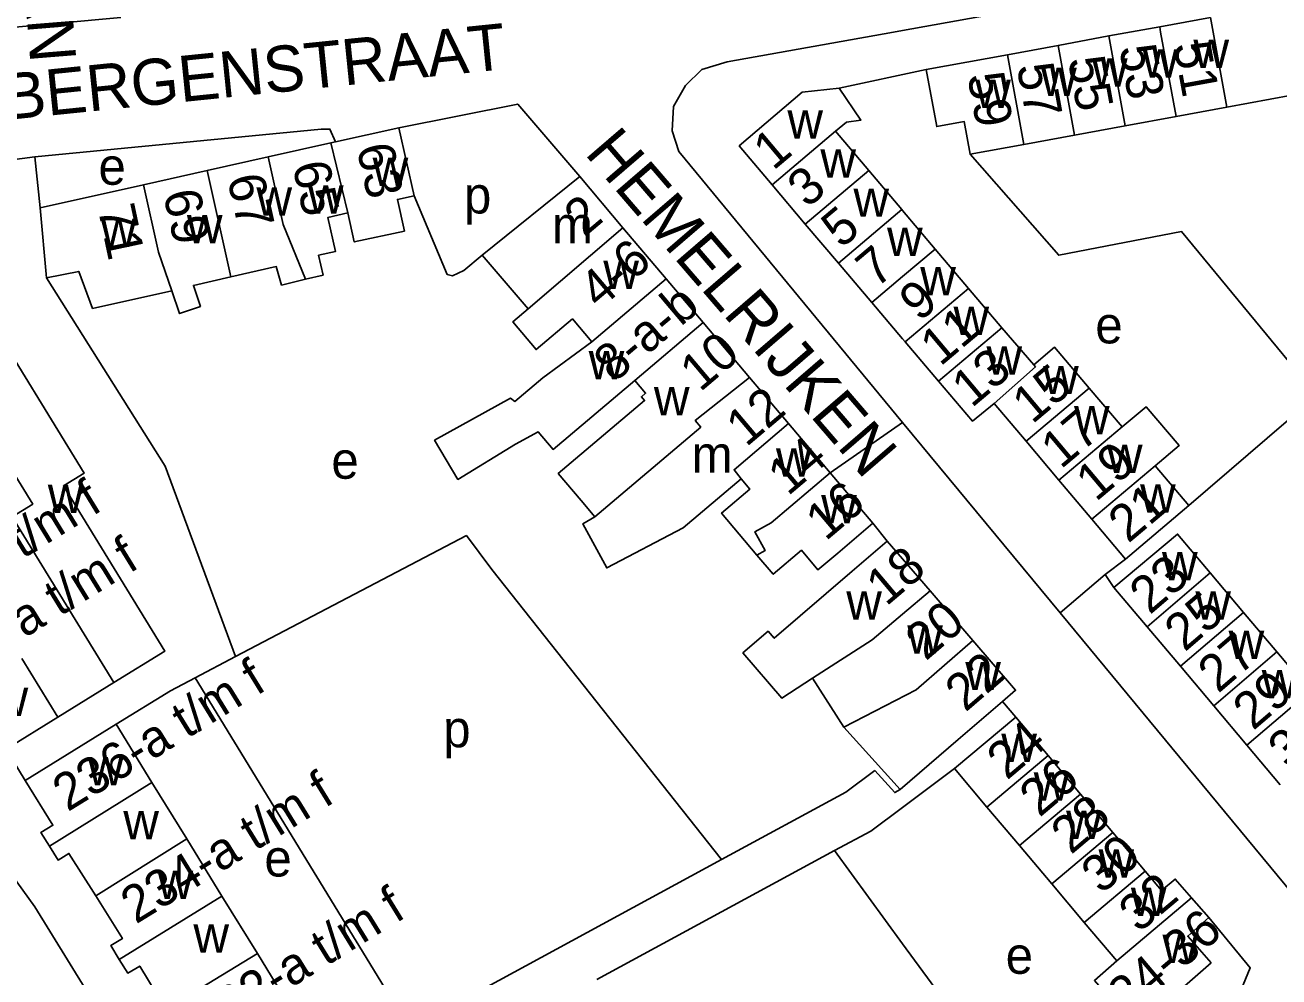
# Model space of a CAD drawing. Extents: x 159902 to 161769, y 383692 to 384875.
# Drawn here: x 160604.7 to 160740.8, y 384397.4 to 384500.8 of the extents above; entities that cross this region are included whole.
import ezdxf

# ---------------------------------------------------------------- set-up
doc = ezdxf.new("R2010")
doc.units = 0
for name, color, linetype in [('BLT_Basislijn', 7, 'Continuous'), ('BLT_Bebouwing', 7, 'Continuous'), ('BLT_Centroide', 7, 'Continuous'), ('BLT_Huisnummer', 7, 'Continuous'), ('BLT_Huisnummer_ tussenligend', 7, 'Continuous'), ('BLT_Huisnummer_reeks', 7, 'Continuous'), ('BLT_Onderverdeling_panden', 7, 'Continuous'), ('BLT_Straatnaam', 7, 'Continuous'), ('BLT_Vlakafsluiter', 7, 'Continuous')]:
    doc.layers.add(name, color=color, linetype=linetype)

msp = doc.modelspace()

# ---------------------------------------------------------------- linework, layer by layer
at = {"layer": 'BLT_Basislijn'}
for p, q in [((160700, 384500.18), (160699, 384500)), ((160702.56, 384495.92), (160693.11, 384493.92)), ((160595.93, 384485.18), (160605.79, 384486.44)), ((160731.05, 384448.61), (160744.94, 384460.54)), ((160700, 384457.63), (160717.09, 384436.96)), ((160696.77, 384446.67), (160698.32, 384444.75)), ((160655.4, 384441.64), (160680.34, 384410.17)), ((160721.97, 384441.1), (160724.19, 384442.79)), ((160717.09, 384436.96), (160721.97, 384441.1)), ((160722.94, 384439.7), (160721.97, 384441.1)), ((160717.09, 384436.96), (160746.97, 384400.81)), ((160627.59, 384432.2), (160623.2, 384429.9)), ((160614.39, 384429.39), (160608.3, 384425.63)), ((160623.2, 384429.9), (160645.9, 384392.82)), ((160710.85, 384427.34), (160712.27, 384425.64)), ((160604.77, 384418.77), (160602.68, 384422.17)), ((160700, 384415.84), (160705.63, 384420.04)), ((160666.8, 384397.15), (160692.62, 384411.14)), ((160692.62, 384411.14), (160700, 384401.04)), ((160646.52, 384391.81), (160680.34, 384410.17)), ((160700, 384401.04), (160706.82, 384391.71))]:
    msp.add_line(p, q, dxfattribs=at)
for points in [[(160758.87, 384500), (160751.1, 384509.34), (160700, 384500.18)], [(160699, 384500), (160680.95, 384496.77), (160678.22, 384495.92), (160676.42, 384494.2), (160675.14, 384491.91), (160674.99, 384489.28), (160675.71, 384487.02), (160700, 384457.63)], [(160664.95, 384484.33), (160658.23, 384492.18), (160645.33, 384489.61)], [(160638.44, 384488.07), (160637.84, 384489.47), (160636.89, 384489.44), (160605.79, 384486.44)], [(160707.33, 384486.73), (160716.95, 384475.77), (160730.27, 384478.33), (160744.94, 384460.54)], [(160605.79, 384486.44), (160606.39, 384480.92)], [(160646.98, 384482.23), (160650.55, 384473.68), (160651.15, 384473.52), (160652.37, 384474.11), (160654.36, 384475.79)], [(160607.09, 384473.32), (160619.95, 384452.88), (160627.59, 384432.2)], [(160655.4, 384441.64), (160652.65, 384445.34), (160627.59, 384432.2)], [(160623.2, 384429.9), (160620.54, 384428.5), (160614.63, 384424.85)], [(160680.34, 384410.17), (160693.84, 384417.49), (160696.99, 384419.84)], [(160699.73, 384417.78), (160699.14, 384417.45), (160696.99, 384419.84)], [(160692.62, 384411.14), (160696.54, 384413.26), (160700, 384415.84)], [(160644.83, 384338.21), (160643.59, 384342.14), (160640.8, 384348.26), (160626.55, 384371.32), (160620.56, 384381.08), (160605.79, 384405.03), (160602.56, 384409.58), (160597.68, 384415)], [(160736.44, 384395.35), (160737.72, 384398.4), (160733.22, 384403.87)]]:
    msp.add_lwpolyline(points, dxfattribs=at)
at = {"layer": 'BLT_Bebouwing'}
for p, q in [((160733.41, 384501.57), (160727.9, 384500.58)), ((160727.9, 384500.58), (160722.39, 384499.57)), ((160722.39, 384499.57), (160716.88, 384498.55)), ((160711.38, 384497.54), (160702.56, 384495.92)), ((160716.88, 384498.55), (160711.38, 384497.54)), ((160693.11, 384493.92), (160689.09, 384493.46)), ((160724.17, 384489.83), (160729.67, 384490.84)), ((160729.67, 384490.84), (160735.18, 384491.85)), ((160638.44, 384488.07), (160645.33, 384489.61)), ((160696.32, 384484.95), (160692.71, 384489.22)), ((160718.66, 384488.81), (160724.17, 384489.83)), ((160631.12, 384486.44), (160637.94, 384487.96)), ((160637.94, 384487.96), (160638.44, 384488.07)), ((160713.15, 384487.8), (160718.66, 384488.81)), ((160707.33, 384486.73), (160713.15, 384487.8)), ((160624.5, 384484.96), (160631.12, 384486.44)), ((160617.61, 384483.42), (160624.5, 384484.96)), ((160669.64, 384478.75), (160664.95, 384484.33)), ((160699.9, 384480.73), (160696.32, 384484.95)), ((160685.82, 384483.42), (160689.43, 384479.16)), ((160700, 384480.61), (160699.9, 384480.73)), ((160703.54, 384476.43), (160700, 384480.61)), ((160674.34, 384473.2), (160669.64, 384478.75)), ((160689.43, 384479.16), (160693.05, 384474.9)), ((160659.36, 384469.95), (160654.36, 384475.79)), ((160707.15, 384472.16), (160703.54, 384476.43)), ((160693.05, 384474.9), (160696.66, 384470.64)), ((160678.34, 384468.46), (160674.34, 384473.2)), ((160696.66, 384470.64), (160700, 384466.7)), ((160683.38, 384462.5), (160678.34, 384468.46)), ((160714.24, 384463.89), (160710.77, 384467.9)), ((160700, 384466.7), (160700.27, 384466.38)), ((160700.27, 384466.38), (160703.89, 384462.11)), ((160687.62, 384457.51), (160683.38, 384462.5)), ((160723.82, 384457.13), (160720.25, 384461.35)), ((160709.92, 384459.68), (160713.39, 384455.58)), ((160692.14, 384452.15), (160687.62, 384457.51)), ((160713.39, 384455.58), (160716.96, 384451.35)), ((160731.05, 384448.61), (160727.4, 384452.91)), ((160696.77, 384446.67), (160692.14, 384452.15)), ((160716.96, 384451.35), (160720.53, 384447.13)), ((160724.19, 384442.79), (160731.05, 384448.61)), ((160720.53, 384447.13), (160724.19, 384442.79)), ((160700, 384442.8), (160698.32, 384444.75)), ((160702.97, 384439.35), (160700, 384442.8)), ((160737, 384437), (160733.39, 384441.29)), ((160707.61, 384433.95), (160702.97, 384439.35)), ((160740.61, 384432.72), (160737, 384437)), ((160726.54, 384435.43), (160730.15, 384431.15)), ((160744.21, 384428.44), (160740.61, 384432.72)), ((160604.39, 384431.98), (160608.3, 384425.63)), ((160730.15, 384431.15), (160733.76, 384426.86)), ((160693.6, 384424.55), (160690.21, 384429.85)), ((160706.04, 384423.2), (160710.85, 384427.34)), ((160733.76, 384426.86), (160737.37, 384422.58)), ((160608.3, 384425.63), (160602.68, 384422.17)), ((160705.63, 384420.04), (160712.27, 384425.64)), ((160712.27, 384425.64), (160715.78, 384421.46)), ((160614.63, 384424.85), (160604.77, 384418.77)), ((160618.52, 384418.53), (160614.63, 384424.85)), ((160693.6, 384424.55), (160699.73, 384417.78)), ((160706.04, 384423.2), (160699.73, 384417.78)), ((160737.37, 384422.58), (160740.97, 384418.3)), ((160715.78, 384421.46), (160719.3, 384417.28)), ((160709.15, 384415.86), (160705.63, 384420.04)), ((160622.29, 384412.43), (160618.52, 384418.53)), ((160719.3, 384417.28), (160722.81, 384413.1)), ((160712.67, 384411.69), (160709.15, 384415.86)), ((160722.81, 384413.1), (160726.32, 384408.92)), ((160626.12, 384406.2), (160622.29, 384412.43)), ((160716.19, 384407.52), (160712.67, 384411.69)), ((160719.71, 384403.35), (160716.19, 384407.52)), ((160629.97, 384399.96), (160626.12, 384406.2)), ((160731.34, 384406.02), (160723.23, 384399.17)), ((160723.23, 384399.17), (160719.71, 384403.35)), ((160633.67, 384393.94), (160629.97, 384399.96))]:
    msp.add_line(p, q, dxfattribs=at)
for points in [[(160702.56, 384495.92), (160703.7, 384489.74), (160706.68, 384490.28), (160707.33, 384486.73)], [(160689.09, 384493.46), (160682.26, 384487.63), (160685.82, 384483.42)], [(160693.11, 384493.92), (160695.47, 384490.44), (160693.89, 384490.21), (160692.71, 384489.22)], [(160735.18, 384491.85), (160744.6, 384493.58), (160748.37, 384489.06)], [(160645.33, 384489.61), (160646.98, 384482.23)], [(160664.95, 384484.33), (160654.36, 384475.79)], [(160606.39, 384480.92), (160617.61, 384483.42)], [(160639.78, 384480.37), (160640.47, 384477.21), (160645.92, 384478.39), (160645.17, 384481.83), (160646.98, 384482.23)], [(160607.09, 384473.32), (160606.39, 384480.92)], [(160635.19, 384473.16), (160637.09, 384473.62), (160636.61, 384475.76), (160638.44, 384476.17), (160637.61, 384479.88), (160639.78, 384480.37)], [(160627.08, 384473.41), (160632.01, 384474.53), (160632.58, 384472.53), (160635.19, 384473.16)], [(160620.67, 384471.91), (160612.08, 384469.99), (160610.57, 384474.01), (160607.09, 384473.32)], [(160620.67, 384471.91), (160621.51, 384469.43), (160623.78, 384470.21), (160623.01, 384472.49), (160627.08, 384473.41)], [(160710.77, 384467.9), (160707.15, 384472.16)], [(160614.39, 384429.39), (160619.93, 384432.8), (160608.9, 384450.73), (160611.17, 384452.13), (160600.08, 384470.15), (160594.52, 384466.73)], [(160666.26, 384466.37), (160664.15, 384468.86), (160660.21, 384465.53), (160657.68, 384468.53), (160659.36, 384469.95)], [(160594.52, 384466.73), (160605.58, 384448.76), (160603.33, 384447.37), (160614.39, 384429.39)], [(160670.92, 384462.18), (160662.06, 384454.69), (160660.45, 384456.59), (160657.97, 384455.25), (160651.72, 384451.44), (160649.19, 384455.68), (160657.43, 384460.25), (160657.92, 384459.91), (160660.93, 384462.46), (160666.26, 384466.37)], [(160720.25, 384461.35), (160716.49, 384465.78), (160714.24, 384463.89)], [(160714.24, 384463.89), (160714.42, 384463.67)], [(160670.92, 384462.18), (160672.1, 384460.78), (160671.65, 384460.4), (160671.99, 384460), (160662.62, 384452.07), (160665.1, 384449.14), (160666.58, 384447.39)], [(160703.89, 384462.11), (160707.59, 384457.75), (160709.92, 384459.68)], [(160727.4, 384452.91), (160730.01, 384455.1), (160726.43, 384459.32), (160723.82, 384457.13)], [(160682.48, 384451.51), (160676.18, 384446.18), (160667.88, 384441.82), (160665.28, 384446.61), (160666.58, 384447.39)], [(160684.19, 384443.23), (160680.35, 384447.78), (160683.43, 384450.39), (160682.48, 384451.51)], [(160696.77, 384446.67), (160692.95, 384443.44), (160690.8, 384441.62), (160689.02, 384443.74), (160685.96, 384441.15), (160684.19, 384443.23)], [(160690.21, 384429.85), (160686.88, 384427.7), (160682.67, 384432.6), (160685.4, 384434.95), (160686.06, 384434.2), (160694.53, 384441.49), (160698.32, 384444.75)], [(160733.39, 384441.29), (160729.84, 384445.51), (160722.94, 384439.7)], [(160722.94, 384439.7), (160726.54, 384435.43)], [(160710.85, 384427.34), (160712.26, 384428.55), (160707.61, 384433.95)], [(160604.77, 384418.77), (160607.77, 384413.89), (160606.47, 384413.11), (160607.4, 384411.61)], [(160607.4, 384411.61), (160608.33, 384410.12), (160609.51, 384410.83), (160612.41, 384406.22)], [(160726.32, 384408.92), (160728.1, 384406.8), (160729.59, 384408.05), (160731.34, 384406.02)], [(160612.41, 384406.22), (160615.31, 384401.6), (160614.05, 384400.84), (160614.97, 384399.34)], [(160733.22, 384403.87), (160731.34, 384406.02)], [(160733.49, 384398.96), (160730.94, 384401.87), (160733.22, 384403.87)], [(160614.97, 384399.34), (160615.89, 384397.85), (160617.19, 384398.61), (160620.02, 384393.93)], [(160723.23, 384399.17), (160720.82, 384397.03), (160725.36, 384391.84), (160733.49, 384398.96)]]:
    msp.add_lwpolyline(points, dxfattribs=at)
at = {"layer": 'BLT_Onderverdeling_panden'}
for p, q in [((160733.41, 384501.57), (160733.7, 384500)), ((160727.9, 384500.58), (160728, 384500)), ((160722.39, 384499.57), (160724.17, 384489.83)), ((160728, 384500), (160729.67, 384490.84)), ((160733.7, 384500), (160735.18, 384491.85)), ((160711.38, 384497.54), (160713.15, 384487.8)), ((160716.88, 384498.55), (160718.66, 384488.81)), ((160685.82, 384483.42), (160692.71, 384489.22)), ((160639.78, 384480.37), (160637.94, 384487.96)), ((160627.08, 384473.41), (160624.5, 384484.96)), ((160689.43, 384479.16), (160696.32, 384484.95)), ((160693.05, 384474.9), (160699.9, 384480.73)), ((160659.36, 384469.95), (160669.64, 384478.75)), ((160700, 384473.45), (160703.54, 384476.43)), ((160666.26, 384466.37), (160674.34, 384473.2)), ((160696.66, 384470.64), (160700, 384473.45)), ((160700.27, 384466.38), (160707.15, 384472.16)), ((160670.92, 384462.18), (160678.34, 384468.46)), ((160703.89, 384462.11), (160710.77, 384467.9)), ((160709.92, 384459.68), (160714.42, 384463.67)), ((160713.39, 384455.58), (160720.25, 384461.35)), ((160716.96, 384451.35), (160723.82, 384457.13)), ((160720.53, 384447.13), (160727.4, 384452.91)), ((160733.39, 384441.29), (160726.54, 384435.43)), ((160700, 384436.8), (160702.97, 384439.35)), ((160737, 384437), (160730.15, 384431.15)), ((160701.47, 384428.58), (160707.61, 384433.95)), ((160740.61, 384432.72), (160733.76, 384426.86)), ((160693.6, 384424.55), (160701.47, 384428.58)), ((160744.21, 384428.44), (160737.37, 384422.58)), ((160709.15, 384415.86), (160715.78, 384421.46)), ((160607.4, 384411.61), (160618.52, 384418.53)), ((160712.67, 384411.69), (160719.3, 384417.28)), ((160716.19, 384407.52), (160722.81, 384413.1)), ((160612.41, 384406.22), (160622.29, 384412.43)), ((160719.71, 384403.35), (160726.32, 384408.92)), ((160614.97, 384399.34), (160626.12, 384406.2)), ((160620.02, 384393.93), (160629.97, 384399.96))]:
    msp.add_line(p, q, dxfattribs=at)
for points in [[(160635.19, 384473.16), (160632.75, 384479.11), (160631.12, 384486.44)], [(160620.67, 384471.91), (160619.24, 384476.1), (160617.61, 384483.42)], [(160666.58, 384447.39), (160678.08, 384457.11), (160677.49, 384457.82), (160683.38, 384462.5)], [(160682.48, 384451.51), (160681.7, 384452.49), (160687.62, 384457.51)], [(160684.19, 384443.23), (160685.08, 384443.72), (160683.96, 384445.76), (160685.74, 384446.74), (160692.14, 384452.15)], [(160690.21, 384429.85), (160696.7, 384434.02), (160700, 384436.8)]]:
    msp.add_lwpolyline(points, dxfattribs=at)
at = {"layer": 'BLT_Vlakafsluiter'}
for p, q in [((160615.14, 384501.58), (160600.21, 384500.22)), ((160700, 384457.63), (160692.14, 384452.15))]:
    msp.add_line(p, q, dxfattribs=at)

# ---------------------------------------------------------------- texts
at = {"layer": 'BLT_Centroide'}
for s, p in [('w', (160731.56, 384496.08)), ('w', (160726.05, 384495.06)), ('w', (160715.03, 384493.06)), ('w', (160720.55, 384494.06)), ('w', (160707.88, 384491.77)), ('w', (160687.49, 384488.44)), ('e', (160612.71, 384483.42)), ('w', (160691.07, 384484.19)), ('w', (160642.47, 384483.28)), ('w', (160629.86, 384480.06)), ('w', (160635.45, 384480.28)), ('p', (160652.38, 384480.3)), ('w', (160694.66, 384479.94)), ('w', (160612.97, 384476.66)), ('w', (160622.31, 384477.06)), ('m', (160661.94, 384477.06)), ('w', (160698.31, 384475.69)), ('w', (160667.51, 384472.12)), ('w', (160701.91, 384471.41)), ('w', (160705.52, 384467.12)), ('e', (160720.91, 384466.2)), ('w', (160665.92, 384462.31)), ('w', (160709.1, 384462.81)), ('w', (160715.25, 384460.69)), ('w', (160673, 384458.38)), ('w', (160718.6, 384456.34)), ('m', (160677.09, 384452.16)), ('w', (160722.17, 384452.12)), ('e', (160637.99, 384451.51)), ('w', (160686.25, 384451.75)), ('w', (160607.22, 384447.78)), ('w', (160691.16, 384446.66)), ('w', (160725.77, 384447.84)), ('w', (160728.15, 384440.47)), ('w', (160693.88, 384436.22)), ('w', (160731.77, 384436.22)), ('w', (160700.5, 384432.53)), ('w', (160735.38, 384431.94)), ('w', (160706.8, 384428.56)), ('w', (160738.98, 384427.66)), ('w', (160601.22, 384425.75)), ('p', (160650.13, 384422.36)), ('w', (160710.71, 384420.75)), ('w', (160611.56, 384418.22)), ('w', (160714.23, 384416.56)), ('w', (160615.41, 384412.38)), ('w', (160717.74, 384412.41)), ('e', (160630.72, 384408.33)), ('w', (160721.26, 384408.22)), ('w', (160619.12, 384405.88)), ('w', (160724.77, 384404.06)), ('w', (160623.02, 384400.06)), ('e', (160711.18, 384397.77)), ('w', (160728.2, 384398.94))]:
    msp.add_text(s, height=4, dxfattribs=at).set_placement(p)
at = {"layer": 'BLT_Huisnummer'}
for s, rotation, p in [('53', 280.3225, (160723.49, 384498.31)), ('59', 280.3225, (160707.01, 384495.29)), ('63', 282.573, (160640.7, 384487.48)), ('1', 40.0727, (160685.95, 384484.89)), ('67', 282.5712, (160626.66, 384484.16)), ('71', 282.0197, (160612.62, 384480.87)), ('2', 40.2176, (160665.43, 384477.66)), ('5', 40.072, (160693.33, 384476.42)), ('9', 40.076, (160701.8, 384468.47)), ('13', 40.0664, (160707.49, 384459.13)), ('12', 40.2165, (160683.01, 384454.88)), ('17', 40.0705, (160717.17, 384452.48)), ('16', 40.21, (160691.64, 384444.67)), ('21', 40.0664, (160724.48, 384444.43)), ('23', 40.5495, (160726.82, 384436.68)), ('20', 40.7166, (160702.5, 384431.66)), ('27', 40.5495, (160734.24, 384428.14)), ('31', 40.4715, (160741.85, 384419.87)), ('24', 40.1467, (160711.31, 384418.72)), ('28', 40.1449, (160718.27, 384410.64)), ('32', 40.0069, (160725.63, 384402.13))]:
    msp.add_text(s, height=4, rotation=rotation, dxfattribs=at).set_placement(p)
at = {"layer": 'BLT_Huisnummer_ tussenligend'}
for s, rotation, p in [('51', 280.3225, (160729.38, 384498.62)), ('57', 280.3225, (160712.37, 384496.3)), ('55', 280.3225, (160717.93, 384497.04)), ('65', 282.573, (160633.74, 384485.56)), ('3', 40.0727, (160689.65, 384480.81)), ('69', 282.5712, (160619.71, 384482.48)), ('7', 40.072, (160697.11, 384472.11)), ('11', 40.076, (160704.08, 384463.63)), ('10', 40.2165, (160678.01, 384460.85)), ('15', 40.0664, (160714.06, 384457.36)), ('14', 40.2165, (160687.54, 384449.56)), ('19', 40.0705, (160720.97, 384448.94)), ('18', 40.21, (160698.21, 384437.59)), ('25', 40.5495, (160730.61, 384432.64)), ('22', 40.7166, (160706.81, 384426.1)), ('29', 40.5495, (160738.04, 384424.1)), ('26', 40.1467, (160714.85, 384414.68)), ('30', 40.1449, (160721.56, 384406.33))]:
    msp.add_text(s, height=4, rotation=rotation, dxfattribs=at).set_placement(p)
at = {"layer": 'BLT_Huisnummer_reeks'}
for s, rotation, p in [('4-6', 40.2176, (160667.06, 384469.81)), ('8-a-b', 40.2184, (160668.64, 384461.83)), ('240-a t/m f', 31.4414, (160591.52, 384434.86)), ('238-a t/m f', 31.6007, (160595.56, 384428.57)), ('236-a t/m f', 31.6007, (160609.37, 384415.3)), ('234-a t/m f', 31.6007, (160616.77, 384403.11)), ('232-a t/m f', 31.6007, (160624.49, 384390.61)), ('34-36', 40.1731, (160724.45, 384393.24))]:
    msp.add_text(s, height=4, rotation=rotation, dxfattribs=at).set_placement(p)
at = {"layer": 'BLT_Straatnaam'}
for s, rotation, p in [('ZEEHELDENLAAN', 274.6244, (160600.69, 384553.95)), ('VAN KINSBERGENSTRAAT', 5.8321, (160571.74, 384487.28)), ('HEMELRIJKEN', 310.713, (160665.39, 384486.8))]:
    msp.add_text(s, height=5, rotation=rotation, dxfattribs=at).set_placement(p)

doc.saveas('drawing.dxf')
